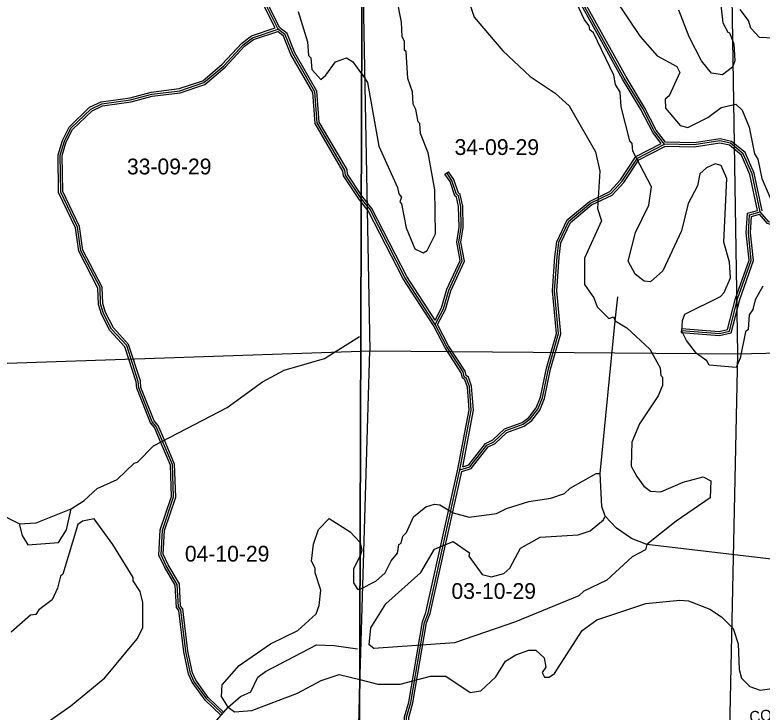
# Model space of a CAD drawing. Extents: x 418523 to 616617, y 1878279 to 2196743.
# Drawn here: x 532209 to 542858, y 1934502 to 1944432 of the extents above; entities that cross this region are included whole.
import ezdxf

# ---------------------------------------------------------------- set-up
doc = ezdxf.new("R2010")
doc.units = 0
for name, color, linetype in [('Level 1', 7, 'Continuous'), ('Level 2', 7, 'Continuous'), ('Level 28', 7, 'Continuous'), ('Level 31', 7, 'Continuous'), ('Level 32', 7, 'Continuous'), ('Level 5', 7, 'Continuous'), ('Level 63', 7, 'Continuous'), ('Level 7', 7, 'Continuous')]:
    doc.layers.add(name, color=color, linetype=linetype)

msp = doc.modelspace()

# ---------------------------------------------------------------- linework, layer by layer
at = {"layer": 'Level 1'}
for p, q in [((537166.409, 1944906.157), (537269.563, 1939647.155)), ((542425.056, 1944958.031), (542510.069, 1939605.013)), ((532099.5, 1939472.416), (537138.246, 1939642.716)), ((537122.342, 1934711.462), (537269.563, 1939647.155)), ((537138.247, 1939642.716), (537269.563, 1939647.155)), ((537269.563, 1939647.155), (542510.069, 1939605.013)), ((542510.069, 1939605.013), (547776.835, 1939742.916)), ((542510.069, 1939605.013), (542392.857, 1934216.367)), ((537110.385, 1934310.618), (537122.34, 1934711.345)), ((537122.34, 1934711.352), (537122.341, 1934711.354)), ((537122.34, 1934711.345), (537122.34, 1934711.352)), ((537122.342, 1934711.46), (537122.342, 1934711.462)), ((537122.342, 1934711.457), (537122.342, 1934711.46)), ((537122.342, 1934711.454), (537122.342, 1934711.457)), ((537122.342, 1934711.451), (537122.342, 1934711.454)), ((537122.342, 1934711.447), (537122.342, 1934711.451)), ((537122.342, 1934711.443), (537122.342, 1934711.447)), ((537122.342, 1934711.438), (537122.342, 1934711.443)), ((537122.342, 1934711.433), (537122.342, 1934711.438)), ((537122.342, 1934711.427), (537122.342, 1934711.433)), ((537122.342, 1934711.421), (537122.342, 1934711.427)), ((537122.342, 1934711.413), (537122.342, 1934711.421)), ((537122.342, 1934711.405), (537122.342, 1934711.413)), ((537122.342, 1934711.396), (537122.342, 1934711.405)), ((537122.342, 1934711.385), (537122.342, 1934711.396)), ((537122.342, 1934711.373), (537122.342, 1934711.385)), ((537122.342, 1934711.36), (537122.342, 1934711.373)), ((537122.342, 1934711.356), (537122.342, 1934711.36)), ((537122.342, 1934711.355), (537122.342, 1934711.356)), ((537122.342, 1934711.354), (537122.342, 1934711.355))]:
    msp.add_line(p, q, dxfattribs=at)
at = {"layer": 'Level 31'}
msp.add_line((537270.13, 1941658.552), (537145.262, 1941817.422), dxfattribs=at)
for points in [[(535962.111, 1944231.269), (535780.048, 1944590.425), (535664.075, 1944765.721), (535623.021, 1944932.771), (535531.82, 1945107.987), (535349.329, 1945334.049), (535241.7, 1945534.411), (535233.661, 1945600.986), (535142.437, 1945768.201), (535060.115, 1946035.393)], [(541465.476, 1942589.307), (541324.406, 1942773.026), (541158.376, 1943098.648), (540892.971, 1943532.95), (539673.473, 1945736.878), (539606.919, 1945878.912), (539540.946, 1946104.221)], [(534311.727, 1938361.883), (534223.48, 1938569.092), (534165.259, 1938635.833), (533975.341, 1939120.119), (533967.387, 1939211.786), (533802.648, 1939721.081), (533586.82, 1939955.262), (533471.01, 1940180.748), (533429.848, 1940314.346), (533422.366, 1940547.835), (533149.081, 1941073.86), (533100.331, 1941407.491), (532860.638, 1941908.678), (532854.135, 1942433.815), (532913.237, 1942633.626), (533005.628, 1942816.598), (533290.137, 1943090.935), (533448.854, 1943165.318), (533857.442, 1943222.145), (534157.82, 1943304.426), (534558.122, 1943352.925), (534900.526, 1943468.166), (535184.907, 1943709.061), (535460.899, 1944007.806), (535594.92, 1944107.372), (535962.111, 1944231.269)], [(537145.261, 1941817.422), (537145.194, 1941817.508), (536921.424, 1942151.699), (536913.065, 1942218.638), (536515.74, 1942895.227), (536483.828, 1943337.169), (536169.293, 1943880.396), (536061.871, 1944147.304), (535962.111, 1944231.269)], [(542830.327, 1941626.866), (542714.805, 1942169.061), (542590.55, 1942452.728), (542407.771, 1942603.48), (542257.661, 1942637.036), (541890.681, 1942579.623), (541465.476, 1942589.307)], [(538552.176, 1937953.559), (538693.965, 1937994.927), (538936.649, 1938302.896), (539036.537, 1938352.399), (539203.786, 1938510.42), (539454.036, 1938601.631), (539554.319, 1938676.226), (539663.071, 1938817.707), (539730.268, 1938976.046), (539814.794, 1939392.524), (539957.701, 1939892.459), (539901.179, 1940501.026), (539935.731, 1940984.573), (539961.16, 1941192.865), (540103.746, 1941492.429), (540412.931, 1941750.014), (540705.232, 1941890.922), (540863.936, 1942065.706), (541081.537, 1942390.131), (541465.476, 1942589.307)], [(538199.24, 1940022.045), (538316.516, 1940246.771), (538392.32, 1940513.448), (538585.155, 1940929.578), (538535.827, 1941196.656), (538569.837, 1941404.92), (538562.218, 1941704.957), (538529.351, 1941855.25), (538504.315, 1941872.058), (538437.944, 1942072.278), (538363.34, 1942180.885)], [(538199.24, 1940022.045), (537767.539, 1940690.002), (537270.13, 1941658.552)], [(541708.458, 1939937.533), (542250.469, 1939894.399), (542392.221, 1939927.417), (542510.191, 1940385.618), (542703.391, 1940935.227), (542662.674, 1941327.369), (542679.982, 1941585.508), (542830.327, 1941626.866)], [(544979.721, 1941195.945), (544863.342, 1941254.843), (543154.602, 1941425.862), (542954.704, 1941485.024), (542830.327, 1941626.866)], [(538552.176, 1937953.559), (538712.734, 1938803.628), (538688.704, 1939137.173), (538647.152, 1939254.037), (538613.883, 1939278.871), (538597.581, 1939345.836), (538364.967, 1939704.774), (538199.24, 1940022.045)], [(535162.925, 1934480.01), (534942.529, 1934689.832), (534760.071, 1934940.624), (534710.558, 1935049.156), (534644.896, 1935366.111), (534572.2, 1935958.376), (534538.985, 1936000.306), (534523.512, 1936317.096), (534366.212, 1936584.172), (534291.775, 1936742.971), (534309.765, 1937093.108), (534469.823, 1937567.509), (534454.819, 1938026.123), (534311.727, 1938361.883)], [(537948.892, 1933745.498), (537899.076, 1933862.39), (537807.887, 1933954.321), (537783.06, 1934037.677), (537792.256, 1934429.3), (537851.371, 1934637.846), (538046.243, 1935779.086), (538096.538, 1935912.385), (538552.176, 1937953.559)]]:
    msp.add_lwpolyline(points, dxfattribs=at)
at = {"layer": 'Level 32'}
for p, q in [((538338.611, 1942163.898), (538388.069, 1942197.871)), ((537244.761, 1941642.281), (537145.106, 1941769.072)), ((541710.838, 1939967.439), (541706.079, 1939907.626))]:
    msp.add_line(p, q, dxfattribs=at)
for points in [[(541419.868, 1942599.443), (541298.932, 1942756.942), (541132.174, 1943083.991), (540867.034, 1943517.858), (539646.736, 1945723.236), (539578.775, 1945868.27), (539518.126, 1946075.398)], [(541480.521, 1942618.972), (541349.881, 1942789.11), (541184.578, 1943113.306), (540918.908, 1943548.041), (539700.211, 1945750.521), (539635.062, 1945889.555), (539574.67, 1946095.81)], [(535919.684, 1944248.615), (535754.072, 1944575.316), (535636.183, 1944753.507), (535594.746, 1944922.114), (535506.592, 1945091.476), (535324.225, 1945317.384), (535212.593, 1945525.197), (535204.568, 1945591.672), (535114.655, 1945756.483), (535038.092, 1946004.986)], [(535986.108, 1944250.285), (535806.025, 1944605.534), (535691.967, 1944777.934), (535651.295, 1944943.429), (535557.046, 1945124.499), (535374.433, 1945350.714), (535270.805, 1945543.624), (535262.755, 1945610.299), (535170.22, 1945779.92), (535100.457, 1946006.349)], [(534284.125, 1938350.128), (534197.743, 1938552.957), (534139.23, 1938620.034), (533945.828, 1939113.204), (533937.793, 1939205.796), (533776.129, 1939705.587), (533561.996, 1939937.929), (533443.116, 1940169.391), (533399.991, 1940309.36), (533392.599, 1940540.056), (533120.127, 1941064.517), (533071.303, 1941398.653), (532830.721, 1941901.698), (532824.08, 1942437.977), (532885.236, 1942644.732), (532981.141, 1942834.663), (533272.897, 1943115.986), (533440.23, 1943194.408), (533851.387, 1943251.592), (534152.023, 1943333.944), (534551.464, 1943382.338), (534885.515, 1943494.767), (535164.116, 1943730.766), (535440.761, 1944030.219), (535580.835, 1944134.282), (535919.684, 1944248.615)], [(537145.434, 1941871.07), (536950.312, 1942162.478), (536942.068, 1942228.495), (536545.158, 1942904.377), (536513.253, 1943346.222), (536196.326, 1943893.58), (536086.91, 1944165.441), (535986.108, 1944250.285)], [(534339.33, 1938373.637), (534249.216, 1938585.227), (534191.288, 1938651.632), (534004.854, 1939127.033), (533996.98, 1939217.776), (533829.168, 1939736.574), (533611.643, 1939972.596), (533498.902, 1940192.105), (533459.705, 1940319.331), (533452.134, 1940555.613), (533178.035, 1941083.201), (533129.359, 1941416.331), (532890.554, 1941915.659), (532884.19, 1942429.653), (532941.238, 1942622.521), (533030.115, 1942798.534), (533307.377, 1943065.882), (533457.479, 1943136.228), (533863.497, 1943192.698), (534163.619, 1943274.91), (534564.78, 1943323.511), (534915.537, 1943441.563), (535205.698, 1943687.355), (535481.036, 1943985.391), (535609.005, 1944080.461), (535955.71, 1944197.446)], [(537145.105, 1941769.072), (537120.901, 1941799.867), (536892.535, 1942140.921), (536884.062, 1942208.781), (536486.322, 1942886.077), (536454.404, 1943328.116), (536142.259, 1943867.213), (536036.831, 1944129.166), (535955.709, 1944197.445)], [(542858.04, 1941640.766), (542743.51, 1942178.301), (542615.158, 1942471.32), (542421.322, 1942631.191), (542258.649, 1942667.556), (541888.688, 1942609.677), (541480.521, 1942618.972)], [(538577.595, 1937929.723), (538711.585, 1937968.817), (538956.028, 1938279.016), (539053.88, 1938327.51), (539219.883, 1938484.356), (539468.426, 1938574.945), (539575.566, 1938654.641), (539689.191, 1938802.461), (539759.067, 1938967.112), (539843.961, 1939385.407), (539988.095, 1939889.626), (539931.279, 1940501.346), (539965.602, 1940981.684), (539990.346, 1941184.381), (540128.006, 1941473.592), (540429.292, 1941724.596), (540723.519, 1941866.432), (540887.626, 1942047.167), (541102.172, 1942367.038), (541472.472, 1942559.138)], [(538590.735, 1937996.06), (538676.344, 1938021.038), (538917.27, 1938326.774), (539019.195, 1938377.287), (539187.688, 1938536.483), (539439.646, 1938628.317), (539533.071, 1938697.812), (539636.951, 1938832.954), (539701.469, 1938984.981), (539785.626, 1939399.641), (539927.308, 1939895.291), (539871.079, 1940500.705), (539905.861, 1940987.462), (539931.972, 1941201.349), (540079.486, 1941511.266), (540396.571, 1941775.432), (540686.946, 1941915.411), (540840.246, 1942084.244), (541060.902, 1942413.223), (541419.867, 1942599.443)], [(542795.091, 1941648.287), (542686.099, 1942159.823), (542565.941, 1942434.137), (542394.221, 1942575.768), (542256.673, 1942606.516), (541892.675, 1942549.569), (541472.472, 1942559.139)], [(538233.085, 1940022.05), (538344.533, 1940235.613), (538420.532, 1940502.976), (538616.391, 1940925.633), (538566.277, 1941196.971), (538599.9, 1941402.866), (538592.136, 1941708.575), (538556.082, 1941873.438), (538529.561, 1941891.243), (538465.081, 1942085.757), (538388.069, 1942197.871)], [(538196.475, 1940081.591), (538288.498, 1940257.928), (538364.107, 1940523.921), (538553.918, 1940933.524), (538505.377, 1941196.339), (538539.775, 1941406.975), (538532.3, 1941701.339), (538502.619, 1941837.062), (538479.069, 1941852.872), (538410.806, 1942058.799), (538338.611, 1942163.898)], [(537295.5, 1941674.822), (537169.488, 1941835.148), (537145.435, 1941871.07)], [(538196.475, 1940081.591), (537793.546, 1940705.034), (537295.5, 1941674.822)], [(538173.291, 1940006.924), (537741.533, 1940674.97), (537244.761, 1941642.281)], [(541706.079, 1939907.626), (542252.736, 1939864.123), (542416.739, 1939902.325), (542538.922, 1940376.887), (542733.926, 1940931.63), (542692.779, 1941327.918), (542708.49, 1941562.236), (542820.162, 1941592.955)], [(541710.838, 1939967.439), (542248.203, 1939924.675), (542367.702, 1939952.51), (542481.461, 1940394.349), (542672.856, 1940938.826), (542632.569, 1941326.819), (542651.474, 1941608.781), (542795.091, 1941648.287)], [(544949.681, 1941177.523), (544854.788, 1941225.548), (543148.801, 1941396.292), (542937.869, 1941458.72), (542820.162, 1941592.954)], [(538522.789, 1937959.611), (538682.531, 1938805.363), (538659.074, 1939130.958), (538621.928, 1939235.429), (538587.286, 1939261.287), (538569.636, 1939333.792), (538339.027, 1939689.638), (538173.291, 1940006.924)], [(538590.735, 1937996.06), (538742.937, 1938801.894), (538718.335, 1939143.389), (538672.376, 1939272.646), (538640.479, 1939296.456), (538625.526, 1939357.878), (538390.907, 1939719.91), (538233.085, 1940022.05)], [(535183.61, 1934501.738), (534965.187, 1934709.683), (534786.11, 1934955.828), (534739.251, 1935058.541), (534674.523, 1935370.991), (534600.95, 1935970.398), (534568.481, 1936011.386), (534553.115, 1936325.948), (534392.778, 1936598.182), (534322.12, 1936748.916), (534339.514, 1937087.436), (534499.985, 1937563.062), (534484.619, 1938032.718), (534339.326, 1938373.644)], [(535142.239, 1934458.281), (534919.871, 1934669.981), (534734.032, 1934925.42), (534681.865, 1935039.77), (534615.269, 1935361.233), (534543.45, 1935946.355), (534509.49, 1935989.225), (534493.908, 1936308.246), (534339.645, 1936570.163), (534261.43, 1936737.024), (534280.015, 1937098.779), (534439.66, 1937571.955), (534425.018, 1938019.529), (534284.129, 1938350.121)], [(537901.318, 1933780.609), (537873.731, 1933845.341), (537781.285, 1933938.541), (537752.956, 1934033.65), (537762.352, 1934433.815), (537822.069, 1934644.481), (538017.156, 1935786.978), (538067.72, 1935920.991), (538522.788, 1937959.611)], [(537963.722, 1933787.226), (537924.423, 1933879.438), (537834.491, 1933970.102), (537813.163, 1934041.706), (537822.159, 1934424.786), (537880.672, 1934631.211), (538075.331, 1935771.194), (538125.356, 1935903.778), (538577.595, 1937929.723)]]:
    msp.add_lwpolyline(points, dxfattribs=at)
at = {"layer": 'Level 5'}
for p, q in [((540765.731, 1940073.706), (540800.186, 1940415.366)), ((540550.371, 1937898.563), (540765.731, 1940073.706)), ((532269.991, 1937183.207), (531903.81, 1937367.777)), ((544755.644, 1936467.884), (541214.011, 1936887.748))]:
    msp.add_line(p, q, dxfattribs=at)
for points in [[(533012.644, 1937397.592), (533196.406, 1937513.687), (533380.357, 1937688.164), (533664.221, 1937812.321), (533906.693, 1938044.959), (533956.774, 1938061.471), (534182.605, 1938294.169), (535234.749, 1938840.996), (535736.104, 1939206.161), (536045.078, 1939371.908), (536620.838, 1939536.81), (537122.034, 1939851.984)], [(540623.431, 1937289.78), (540573.868, 1937431.662), (540550.371, 1937898.563)], [(532269.991, 1937183.207), (532511.816, 1937199.131), (533012.644, 1937397.592)], [(532269.991, 1937183.207), (532311.155, 1937016.344), (532394.09, 1936882.702), (532827.678, 1936914.678), (532944.978, 1937097.684), (533012.644, 1937397.592)], [(541214.011, 1936887.748), (540997.555, 1936971.796), (540781.267, 1937122.567), (540623.431, 1937289.78)], [(535246.078, 1934572.716), (535421.63, 1934722.181), (535571.882, 1934788.415), (535672.57, 1934996.501), (535781.231, 1935079.504), (536507.701, 1935460.652), (536757.766, 1935451.506), (537091.055, 1935400.439)], [(532742.3, 1933680.401), (533067.416, 1933687.686), (533734.59, 1933760.596), (534085.234, 1933926.175), (534485.671, 1934016.602), (534953.198, 1934231.843), (535246.078, 1934572.716)]]:
    msp.add_lwpolyline(points, dxfattribs=at)
at = {"layer": 'Level 63'}
for points in [[(497370.053, 1923990.389), (537087.279, 1923840.983), (537233.896, 1969297.112), (497565.655, 1969446.889), (497370.053, 1923990.389)], [(537087.28, 1923840.983), (576804.214, 1923734.416), (576901.847, 1969190.287), (537233.897, 1969297.112), (537087.28, 1923840.983)]]:
    msp.add_lwpolyline(points, dxfattribs=at)
at = {"layer": 'Level 7'}
for p, q in [((537129.456, 1936916.68), (537129.456, 1936916.679)), ((537129.456, 1936916.679), (537129.456, 1936916.678)), ((537129.456, 1936916.678), (537129.456, 1936916.677)), ((537129.456, 1936916.677), (537129.456, 1936916.676)), ((537129.456, 1936916.676), (537129.456, 1936916.675)), ((537129.456, 1936916.676), (537129.456, 1936916.676)), ((537129.456, 1936916.675), (537129.456, 1936916.674)), ((537129.456, 1936916.674), (537129.456, 1936916.673)), ((537129.456, 1936916.673), (537129.456, 1936916.672)), ((537129.456, 1936916.672), (537129.456, 1936916.671)), ((537129.456, 1936916.671), (537129.456, 1936916.67)), ((537129.456, 1936916.671), (537129.456, 1936916.671)), ((537129.456, 1936916.67), (537129.456, 1936916.669)), ((537129.456, 1936916.669), (537129.456, 1936916.668)), ((537129.456, 1936916.668), (537129.456, 1936916.667)), ((537129.456, 1936916.667), (537129.456, 1936916.666)), ((537129.456, 1936916.666), (537129.456, 1936916.665)), ((537129.456, 1936916.666), (537129.456, 1936916.666)), ((537129.456, 1936916.665), (537129.456, 1936916.664)), ((537129.456, 1936916.664), (537129.456, 1936916.663)), ((537129.456, 1936916.663), (537129.456, 1936916.662)), ((537129.456, 1936916.662), (537129.456, 1936916.661)), ((537129.456, 1936916.661), (537129.456, 1936916.66)), ((537129.456, 1936916.661), (537129.456, 1936916.661)), ((537129.456, 1936916.66), (537129.456, 1936916.659)), ((537129.456, 1936916.659), (537129.456, 1936916.658)), ((537129.456, 1936916.658), (537129.456, 1936916.657)), ((537129.456, 1936916.657), (537129.456, 1936916.656)), ((537129.456, 1936916.656), (537129.456, 1936916.655)), ((537129.456, 1936916.656), (537129.456, 1936916.656)), ((537129.456, 1936916.655), (537129.456, 1936916.654)), ((537129.456, 1936916.654), (537129.456, 1936916.652)), ((537129.456, 1936916.652), (537129.456, 1936916.651)), ((537129.456, 1936916.651), (537129.456, 1936916.649)), ((537129.456, 1936916.649), (537129.456, 1936916.647)), ((537129.456, 1936916.647), (537129.456, 1936916.646)), ((537129.456, 1936916.646), (537129.456, 1936916.644)), ((537129.456, 1936916.644), (537129.456, 1936916.642)), ((537129.456, 1936916.642), (537129.456, 1936916.641)), ((537129.456, 1936916.641), (537129.456, 1936916.639)), ((537129.456, 1936916.639), (537129.456, 1936916.637)), ((537129.456, 1936916.637), (537129.456, 1936916.636)), ((537129.456, 1936916.636), (537129.456, 1936916.634)), ((537129.456, 1936916.634), (537129.456, 1936916.632)), ((537129.456, 1936916.632), (537129.456, 1936916.631)), ((537129.456, 1936916.631), (537129.456, 1936916.629)), ((537129.456, 1936916.629), (537129.456, 1936916.627)), ((537129.456, 1936916.627), (537129.456, 1936916.626)), ((537129.456, 1936916.626), (537129.456, 1936916.624)), ((537129.456, 1936916.624), (537129.456, 1936916.622)), ((537129.456, 1936916.622), (537129.456, 1936916.621)), ((537129.456, 1936916.621), (537129.456, 1936916.619)), ((537129.456, 1936916.619), (537129.456, 1936916.617)), ((537129.456, 1936916.617), (537129.456, 1936916.616)), ((537129.456, 1936916.616), (537129.456, 1936916.614)), ((537129.456, 1936916.614), (537129.456, 1936916.612)), ((537129.456, 1936916.612), (537129.456, 1936916.611))]:
    msp.add_line(p, q, dxfattribs=at)
for points in [[(540572.929, 1944942.789), (541120.524, 1944124.056), (541361.394, 1943848.173), (541644.342, 1943697.204), (541685.755, 1943613.712), (541534.626, 1943280.752), (541476.106, 1943230.931), (541484.048, 1943105.847), (541691.677, 1942855.075), (541799.95, 1942829.736), (542083.844, 1942970.542), (542276.036, 1943111.638), (542484.61, 1943161.002), (542576.053, 1943077.341), (542675.299, 1942835.257), (542749.086, 1942451.559), (542798.879, 1942376.368), (542856.345, 1942101.072), (543021.834, 1941717.076)], [(538630.009, 1944773.939), (538753.847, 1944398.412), (539160.824, 1943921.926), (539551.459, 1943553.883), (539909.171, 1943319.322), (540108.657, 1943135.271), (540481.696, 1942483.82), (540547.512, 1942208.524), (540512.43, 1941675.101), (540570.234, 1941499.838), (540326.776, 1940967.102), (540325.573, 1940591.963), (540458.329, 1940399.801)], [(537150.994, 1943594.476), (537233.659, 1943469.611), (537397.477, 1942560.421), (537662.352, 1941976.021), (537678.724, 1941884.259), (537720.246, 1941834.108), (537695.046, 1941767.516), (537719.957, 1941742.406), (537785.564, 1941400.429), (537909.631, 1941099.893), (538026.176, 1941041.174), (538084.626, 1941074.325), (538202.125, 1941315.722), (538195.775, 1941940.977), (538097.444, 1942466.468), (537989.947, 1942741.923), (537982.065, 1942883.676), (537957.124, 1942908.746), (537924.34, 1943083.911), (537882.918, 1943159.101), (537875.135, 1943334.166), (537809.061, 1943526.129), (537785.264, 1943909.668), (537760.323, 1943926.438), (537760.741, 1944059.821), (537727.599, 1944118.272), (537719.916, 1944326.716), (537654.329, 1944668.704)], [(542868.089, 1940567.116), (542759.1, 1940375.74), (542725.291, 1940234.116), (542675.051, 1940159.254), (542657.724, 1939950.909), (542624.244, 1939917.667), (542548.008, 1939542.788), (542489.229, 1939409.574), (542105.89, 1939444.16), (542072.708, 1939502.611), (541923.013, 1939611.481), (541781.887, 1939795.334), (541715.614, 1939928.916), (541724.441, 1940078.97), (541758.081, 1940170.532), (542267.388, 1940418.995), (542317.598, 1940477.186), (542409.987, 1940685.293), (542394.033, 1940910.448), (542311.576, 1941194.143), (542356.173, 1942102.676), (542273.389, 1942286.339), (542190.096, 1942311.608), (542064.885, 1942253.676), (541972.894, 1942170.612), (541938.996, 1941995.637), (541804.827, 1941745.98), (541711.851, 1941354.46), (541443.294, 1940788.442), (541267.713, 1940630.636), (541176.041, 1940639.266), (541051.326, 1940739.696), (540951.871, 1940923.419), (541053.217, 1941331.581), (541246.195, 1941722.762), (541280.391, 1941981.098), (541015.258, 1942490.457), (541007.246, 1942598.87), (540974.035, 1942640.65), (540850.554, 1943124.55), (540834.541, 1943333.025), (540768.207, 1943441.586), (540743.625, 1943575.069), (540453.779, 1944176.199), (540403.887, 1944218.05), (540395.746, 1944276.431), (540329.323, 1944360.032), (540213.396, 1944602.146)], [(542272.373, 1944570.532), (542296.597, 1944320.337), (542371.171, 1944186.735), (542396.171, 1944178.325), (542454.006, 1944019.742), (542469.9, 1943777.926), (542436.261, 1943686.324), (542294.209, 1943578.41)], [(543256.025, 1944559.025), (543205.098, 1944275.748), (543129.678, 1944150.934), (543029.477, 1944101.241), (542821.102, 1944110.269), (542696.477, 1944244.041), (542663.495, 1944352.512), (542547.28, 1944511.295)], [(536244.87, 1944481.511), (536376.84, 1944047.592), (536392.933, 1943855.788), (536426.145, 1943822.348), (536442.297, 1943655.554), (536566.882, 1943513.442), (536642.103, 1943571.535), (536776.103, 1943762.851), (536934.665, 1943820.715), (537026.199, 1943762.064), (537150.684, 1943594.942), (537150.993, 1943594.476)], [(542294.209, 1943578.41), (542135.885, 1943603.938), (541994.729, 1943779.461), (541820.77, 1944121.806), (541671.931, 1944497.433)], [(540458.329, 1940399.801), (540507.961, 1940274.588), (540674.128, 1940107.346), (540740.919, 1940132.118), (540765.731, 1940073.706)], [(540765.731, 1940073.706), (540932.136, 1939973.106), (541256.297, 1939671.954), (541405.505, 1939404.73), (541413.487, 1939296.327), (541438.428, 1939271.256), (541438.04, 1939154.544), (541379.191, 1939004.65), (541111.151, 1938605.396), (541001.963, 1938347.289), (540992.518, 1938005.531), (541075.392, 1937855.219), (541175.006, 1937721.506), (541266.48, 1937646.186), (541416.493, 1937637.358), (541733.738, 1937778.066), (542017.403, 1937852.181), (542125.606, 1937793.501), (542116.49, 1937551.776), (541631.905, 1937219.861), (541214.011, 1936887.748)], [(537127.306, 1936250.703), (537352.586, 1936366.605), (537486.356, 1936482.89), (537570.276, 1936657.695), (537662.336, 1936765.768), (537679.394, 1936890.751), (537712.815, 1936907.322), (537738.114, 1937007.265), (537788.294, 1937057.116), (537889.052, 1937281.903), (538064.564, 1937423.029), (538189.746, 1937464.321), (538264.768, 1937455.762), (538456.114, 1937338.432), (538681, 1937279.354), (539072.967, 1937328.1), (539214.949, 1937402.664), (539532.025, 1937501.69), (539848.971, 1937550.696), (540040.934, 1937616.77), (540124.525, 1937691.532), (540492.009, 1937898.762), (540550.371, 1937898.563)], [(532168.759, 1934207.456), (532268.731, 1934182.117), (532268.731, 1934182.117), (532627.646, 1934322.695), (533003.63, 1934588.246), (533488.414, 1934986.822), (533948.715, 1935543.891), (534032.564, 1935702.016), (534033.738, 1936060.474), (533992.545, 1936218.997), (533893, 1936369.38), (533893.169, 1936419.401), (533602.895, 1936887.148), (533337.304, 1937254.833), (533170.45, 1937222.011), (533103.63, 1937172.218), (532892.937, 1936464.289), (532859.526, 1936439.378), (532817.259, 1936264.443), (532741.7, 1936097.978), (532549.508, 1935956.882), (532507.638, 1935890.321), (532432.576, 1935882.209), (532156.695, 1935641.34)], [(535246.078, 1934572.716), (535154.864, 1934723.067), (535163.721, 1934889.761), (535406.362, 1935164.071), (535849.167, 1935471.114), (536241.592, 1935661.574), (536500.804, 1935902.513), (536542.843, 1936019.096), (536568.54, 1936235.741), (536485.994, 1936486.096), (536486.223, 1936552.778), (536436.5, 1936652.98), (536462.297, 1936894.676), (536538.005, 1937102.821), (536688.546, 1937260.747), (536988.035, 1937068.036), (537129.261, 1936917.525), (537129.455, 1936916.68)], [(541214.011, 1936887.748), (541197.101, 1936812.786), (541005.049, 1936713.361), (540645.536, 1936381.058), (540319.892, 1936223.711), (540244.641, 1936157.248), (539343.138, 1935785.017), (538475.184, 1935487.689), (537324.501, 1935408.022), (537257.978, 1935458.232), (537283.775, 1935699.928), (537493.254, 1936041.029), (537994.907, 1936489.586), (538187.686, 1936822.426), (538454.811, 1936929.942), (538687.708, 1936770.802), (538679.209, 1936720.821), (538870.126, 1936461.767), (539003.411, 1936427.998), (539178.633, 1936477.461), (539262.224, 1936552.224), (539413.192, 1936835.173), (539697.116, 1936992.651), (540239.117, 1937024.258), (540406, 1937082.061), (540598.261, 1937239.868), (540623.431, 1937289.78)], [(537129.456, 1936916.611), (537153.915, 1936800.752), (537128.841, 1936726.284)], [(537128.84, 1936726.284), (537128.674, 1936725.791), (537036.385, 1936542.685), (537035.738, 1936342.611), (537093.801, 1936250.709), (537127.141, 1936250.619), (537127.305, 1936250.703)], [(537123.166, 1934966.784), (537381.23, 1934899.311), (537698.006, 1934898.295), (538131.884, 1935013.593), (538348.639, 1935012.916), (538698.01, 1934778.385), (538848.133, 1934802.898), (539065.525, 1935002.286), (539199.624, 1935226.912), (539349.976, 1935318.156), (539533.568, 1935384.261), (539633.611, 1935383.931), (539749.985, 1935275.161), (539774.577, 1935141.718), (539724.297, 1935066.856), (539757.439, 1935000.064), (539824.131, 1934999.835), (539899.321, 1935049.627), (540293.09, 1935665.237), (540501.992, 1935814.643), (541202.994, 1936045.808), (541686.663, 1936094.256), (541811.676, 1936085.526), (542111.395, 1935967.868), (542277.79, 1935858.937), (542443.966, 1935691.686), (542518.311, 1935474.711), (542533.807, 1935107.853), (542566.76, 1934982.711), (542683.074, 1934865.609), (542832.968, 1934815.13), (543058.142, 1934847.724)], [(535246.078, 1934572.716), (535337.551, 1934505.735), (535587.706, 1934521.588), (536238.726, 1934769.583), (536572.76, 1934951.911), (536831.455, 1935034.456), (537123.032, 1934966.819), (537123.165, 1934966.784)]]:
    msp.add_lwpolyline(points, dxfattribs=at)

# ---------------------------------------------------------------- texts
at = {"layer": 'Level 2'}
for s, p in [('34-09-29', (538475.157, 1942436.89)), ('33-09-29', (533805.68, 1942160.5)), ('04-10-29', (534631.374, 1936644.828)), ('03-10-29', (538431.047, 1936113.335))]:
    msp.add_text(s, height=225, dxfattribs=at).set_placement(p)
at = {"layer": 'Level 28'}
msp.add_text('COUNTY HWY 13', height=160, rotation=6.0424417, dxfattribs=at).set_placement((542686.445, 1934349.108))

doc.saveas('drawing.dxf')
